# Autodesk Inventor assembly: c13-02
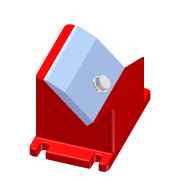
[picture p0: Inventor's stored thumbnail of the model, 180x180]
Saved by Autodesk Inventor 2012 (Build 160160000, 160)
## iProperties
Created: 2010-11
Part Number: c13-02
Document SubType Name: Assembly
Designer: Beta-8540w
Author: Beta-8540w
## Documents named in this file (5)
- C:\Users\VMuser\Desktop\Inventor 2012 Essentials\Assemblies\Chapter 13\c13-02.iam
- C:\Users\VMuser\Desktop\Inventor 2012 Essentials\Content Center Files\en-US\ISO 4017\ISO 4017 - M10 x 35ISO.ipt
- C:\Users\VMuser\Desktop\Inventor 2012 Essentials\Parts\Chapter 13\c13-02.ipt
- C:\Users\VMuser\Desktop\Inventor 2012 Essentials\Content Center Files\en-US\ISO 7091\ISO 7091 - ST 10 - 100 HV.ipt
- C:\Users\VMuser\Desktop\Inventor 2012 Essentials\Parts\Chapter 13\c13-01.ipt
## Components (4 placed, 4 different names)
1. c13-01:1 — Insert:1, Angle:1
2. c13-02:1 — Insert:1, Angle:1, Insert:2
3. ISO 4017 M10 x 35:1 — Insert:3
4. ISO 7091 ST 10 - 100 HV:1 — Insert:2, Insert:3
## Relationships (4: Insert 3, Angle 1)
- Insert:1: c13-01:1 ↔ c13-02:1
- Angle:1: c13-01:1 ↔ c13-02:1
- Insert:2: c13-02:1 ↔ ISO 7091 ST 10 - 100 HV:1
- Insert:3: ISO 4017 M10 x 35:1 ↔ ISO 7091 ST 10 - 100 HV:1
